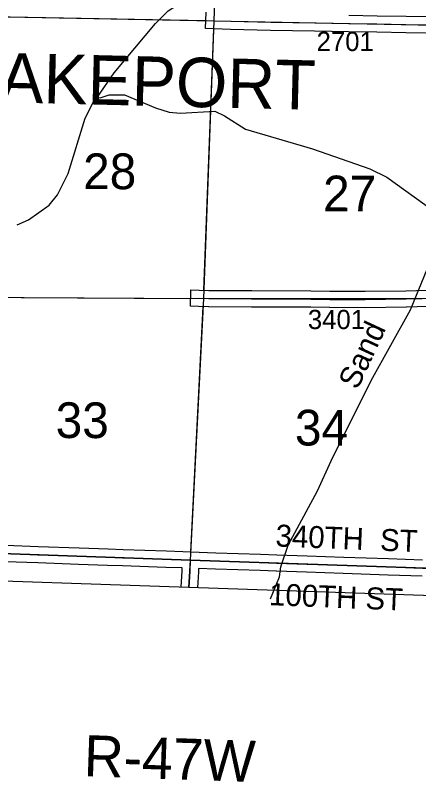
# Model space of a CAD drawing. Extents: x -157.2 to -99.3, y 12.2 to 46.2.
# Drawn here: x -144.708 to -143.24, y 16.379 to 19.169 of the extents above; entities that cross this region are included whole.
import ezdxf

# ---------------------------------------------------------------- set-up
doc = ezdxf.new("R2010")
doc.units = 0
for name, color, linetype in [('tdCoClipBndry', 7, 'Continuous'), ('tdCoCoAdjSecRdTxt', 7, 'Continuous'), ('tdCoCoBndry', 7, 'Continuous'), ('tdCoHydroRiver', 7, 'Continuous'), ('tdCoHydroTxtLg', 7, 'Continuous'), ('tdCoSecRdNmbr', 7, 'Continuous'), ('tdCoSecRdTxt', 7, 'Continuous'), ('tdCoSecRteBand', 7, 'Continuous'), ('tdCoSecRteCL', 7, 'Continuous'), ('tdCoSectLine', 7, 'Continuous'), ('tdCoSectLinePart', 7, 'Continuous'), ('tdCoSectNmbr', 7, 'Continuous'), ('tdCoSurfConc', 7, 'Continuous'), ('tdCoSurfEarth', 7, 'Continuous'), ('tdCoSurfGravel', 7, 'Continuous'), ('tdCoTwpBndryShd', 7, 'Continuous'), ('tdCoTwpNameTxt', 7, 'Continuous'), ('tdCoTwpRngTxt', 7, 'Continuous')]:
    doc.layers.add(name, color=color, linetype=linetype)

msp = doc.modelspace()

# ---------------------------------------------------------------- linework, layer by layer
at = {"layer": 'tdCoClipBndry'}
msp.add_lwpolyline([(-136.1344, 16.7663), (-142.0845, 17.0183), (-145.0729, 17.1202)], dxfattribs=at)
at = {"layer": 'tdCoCoBndry'}
msp.add_lwpolyline([(-146.5016, 17.2735), (-146.0768, 17.2556), (-146.0694, 17.2557), (-145.0695, 17.2201), (-144.0702, 17.1857), (-143.0731, 17.1519), (-142.0807, 17.1182), (-141.0904, 17.0763), (-140.1006, 17.0343), (-139.109, 16.9941), (-138.1248, 16.9495), (-137.1248, 16.9061), (-136.1296, 16.8661), (-135.1553, 16.8138), (-134.1666, 16.7512)], dxfattribs=at)
at = {"layer": 'tdCoHydroRiver'}
for points in [[(-144.4096, 18.8702), (-144.3483, 18.9598), (-144.1971, 19.1395), (-144.1514, 19.1854), (-144.1176, 19.2064), (-144.0962, 19.2309), (-144.0908, 19.2529), (-144.0964, 19.2752), (-144.1172, 19.3138), (-144.1521, 19.356), (-144.221, 19.4688), (-144.2911, 19.5438), (-144.3641, 19.6106)], [(-144.7011, 18.4061), (-144.6595, 18.4237), (-144.5851, 18.4781), (-144.5539, 18.5149), (-144.5151, 18.5926), (-144.4532, 18.7943), (-144.4177, 18.8658), (-144.4096, 18.8702)], [(-144.4096, 18.8702), (-144.3986, 18.8683), (-144.3667, 18.8799), (-144.3099, 18.8795), (-144.1978, 18.8316), (-144.1478, 18.8157), (-144.1069, 18.8128), (-143.9819, 18.8197), (-143.9462, 18.8027), (-143.8704, 18.7544), (-143.6265, 18.6831), (-143.4174, 18.6098), (-143.3553, 18.5793), (-143.1872, 18.4584), (-143.1614, 18.4291), (-143.1331, 18.3776)], [(-143.7788, 17.0444), (-143.7458, 17.125), (-143.7414, 17.1612), (-143.7152, 17.2393), (-143.6076, 17.4379), (-143.5582, 17.5468), (-143.4128, 17.8389), (-143.2702, 18.0963), (-143.1792, 18.3191), (-143.1493, 18.3639), (-143.1331, 18.3776)]]:
    msp.add_lwpolyline(points, dxfattribs=at)
at = {"layer": 'tdCoSecRteBand'}
for points in [[(-143.4944, 19.1691), (-143.3914, 19.1672), (-143.2857, 19.1654), (-143.2857, 19.1654), (-143.2856, 19.1654), (-143.1409, 19.163), (-143.1408, 19.163), (-143.1407, 19.163), (-143.0232, 19.1604), (-143.0212, 19.215)], [(-143.142, 19.103), (-143.2867, 19.1054), (-143.3924, 19.1072), (-143.3925, 19.1072), (-143.3925, 19.1072), (-143.4956, 19.1091), (-143.4956, 19.1091), (-143.4956, 19.1091), (-143.6188, 19.1116), (-143.7788, 19.1138), (-143.7789, 19.1138), (-143.779, 19.1138), (-143.9245, 19.117), (-143.9248, 19.117), (-143.925, 19.117), (-143.9852, 19.1193), (-144.0151, 19.1204), (-144.0129, 19.1803)], [(-143.1675, 18.1095), (-143.2846, 18.1063), (-143.2848, 18.1063), (-143.285, 18.1063), (-143.4347, 18.1043), (-143.435, 18.1043), (-143.4352, 18.1043), (-143.5635, 18.1048), (-143.5636, 18.1048), (-143.5638, 18.1048), (-143.6327, 18.1058), (-143.8478, 18.1068), (-144.0041, 18.1073), (-144.0046, 18.1073), (-144.0051, 18.1073), (-144.0408, 18.1085), (-144.0708, 18.1096), (-144.0687, 18.1695), (-144.0388, 18.1685), (-144.0035, 18.1673), (-143.8476, 18.1668), (-143.8476, 18.1668), (-143.8475, 18.1668), (-143.6323, 18.1658), (-143.6321, 18.1658), (-143.632, 18.1658), (-143.5631, 18.1648), (-143.4352, 18.1643), (-143.286, 18.1663), (-143.1688, 18.1695)], [(-144.7429, 17.2394), (-144.6243, 17.2353), (-144.4753, 17.2301), (-144.4753, 17.2301), (-144.4753, 17.2301), (-144.3702, 17.2264), (-144.3702, 17.2264), (-144.3701, 17.2264), (-144.3157, 17.2242), (-144.158, 17.219), (-144.1579, 17.219), (-144.1579, 17.219), (-144.0987, 17.2168), (-144.0689, 17.2157), (-144.039, 17.2148), (-144.039, 17.2146), (-144.0388, 17.2146), (-143.9777, 17.2123), (-143.8152, 17.2071), (-143.8151, 17.2071), (-143.8151, 17.2071), (-143.7557, 17.2049), (-143.646, 17.2012), (-143.646, 17.2012), (-143.646, 17.2012), (-143.5128, 17.1965), (-143.3493, 17.1909), (-143.2255, 17.1867)], [(-144.1045, 17.0872), (-144.101, 17.1459), (-144.1007, 17.1568), (-144.16, 17.159), (-144.3178, 17.1642), (-144.3179, 17.1642), (-144.318, 17.1642), (-144.3724, 17.1664), (-144.4774, 17.1701), (-144.6263, 17.1753), (-144.6264, 17.1753), (-144.6264, 17.1753), (-144.7448, 17.1795), (-144.8628, 17.1824), (-144.863, 17.1824), (-144.8632, 17.1824), (-144.9731, 17.1866), (-145.0409, 17.189), (-145.0451, 17.1192)], [(-143.2276, 17.1267), (-143.3514, 17.1309), (-143.3514, 17.1309), (-143.3514, 17.1309), (-143.5149, 17.1366), (-143.5149, 17.1366), (-143.5149, 17.1366), (-143.648, 17.1413), (-143.7578, 17.145), (-143.7578, 17.145), (-143.7579, 17.145), (-143.8172, 17.1472), (-143.9797, 17.1524), (-143.9797, 17.1524), (-143.9798, 17.1524), (-144.0408, 17.1546), (-144.0411, 17.1437), (-144.0411, 17.1433), (-144.0411, 17.1428), (-144.0446, 17.0851)]]:
    msp.add_lwpolyline(points, dxfattribs=at)
at = {"layer": 'tdCoSecRteCL'}
for points in [[(-143.9841, 19.1492), (-143.9239, 19.147), (-143.7784, 19.1438), (-143.6183, 19.1416), (-143.495, 19.1391), (-143.3919, 19.1372), (-143.2862, 19.1354), (-143.1414, 19.133), (-142.9942, 19.1297)], [(-144.0398, 18.1385), (-144.004, 18.1373), (-143.8477, 18.1368), (-143.6324, 18.1358), (-143.5633, 18.1348), (-143.4351, 18.1343), (-143.2854, 18.1363), (-143.168, 18.1395), (-143.0519, 18.1403), (-143.0306, 18.1392)], [(-145.0691, 17.2201), (-144.972, 17.2166), (-144.862, 17.2124), (-144.7439, 17.2095), (-144.6253, 17.2053), (-144.4764, 17.2001), (-144.3713, 17.1964), (-144.3168, 17.1942), (-144.159, 17.189), (-144.0699, 17.1857)], [(-144.0746, 17.0861), (-144.0711, 17.1446), (-144.0699, 17.1857)], [(-144.0699, 17.1857), (-143.9787, 17.1823), (-143.8162, 17.1772), (-143.7568, 17.1749), (-143.647, 17.1712), (-143.5138, 17.1666), (-143.3503, 17.1609), (-143.2265, 17.1567), (-143.1222, 17.1532), (-143.0727, 17.1519)]]:
    msp.add_lwpolyline(points, dxfattribs=at)
at = {"layer": 'tdCoSectLine'}
for points in [[(-143.9844, 19.1492), (-143.9501, 20.1393)], [(-144.9877, 19.1678), (-143.9844, 19.1492)], [(-144.0223, 18.1379), (-143.9844, 19.1492)], [(-143.9844, 19.1492), (-142.9946, 19.1297)], [(-144.894, 18.1425), (-144.0223, 18.1379)], [(-144.0702, 17.1857), (-144.0223, 18.1379)], [(-144.0223, 18.1379), (-143.031, 18.1392)], [(-145.0695, 17.2201), (-144.0702, 17.1857)], [(-144.0759, 17.0862), (-144.0702, 17.1857)], [(-144.0702, 17.1857), (-143.0731, 17.1519)]]:
    msp.add_lwpolyline(points, dxfattribs=at)
at = {"layer": 'tdCoSectLinePart'}
for points in [[(-144.9877, 19.1678), (-144.0144, 19.1498)], [(-144.0212, 18.1679), (-143.9856, 19.1193)], [(-144.894, 18.1425), (-144.0702, 18.1382)], [(-144.0687, 17.2161), (-144.0238, 18.108)]]:
    msp.add_lwpolyline(points, dxfattribs=at)
at = {"layer": 'tdCoSurfConc'}
msp.add_lwpolyline([(-144.0398, 18.1385), (-144.004, 18.1373), (-143.8477, 18.1368), (-143.6324, 18.1358), (-143.5633, 18.1348), (-143.4351, 18.1343), (-143.2854, 18.1363), (-143.168, 18.1395), (-143.0519, 18.1403), (-143.0306, 18.1392)], dxfattribs=at)
at = {"layer": 'tdCoSurfEarth'}
msp.add_lwpolyline([(-144.0746, 17.0861), (-144.0711, 17.1446), (-144.0699, 17.1857)], dxfattribs=at)
at = {"layer": 'tdCoSurfGravel'}
for points in [[(-143.9841, 19.1492), (-143.9239, 19.147), (-143.7784, 19.1438), (-143.6183, 19.1416), (-143.495, 19.1391), (-143.3919, 19.1372), (-143.2862, 19.1354), (-143.1414, 19.133), (-142.9942, 19.1297), (-142.9345, 19.1288), (-142.8092, 19.1243), (-142.6879, 19.1209), (-142.5974, 19.1164), (-142.4701, 19.1125), (-142.3853, 19.1093), (-142.2825, 19.1058), (-142.1604, 19.1019), (-142.0383, 19.0984), (-142.0151, 19.0978)], [(-145.0691, 17.2201), (-144.972, 17.2166), (-144.862, 17.2124), (-144.7439, 17.2095), (-144.6253, 17.2053), (-144.4764, 17.2001), (-144.3713, 17.1964), (-144.3168, 17.1942), (-144.159, 17.189), (-144.0699, 17.1857), (-143.9787, 17.1823), (-143.8162, 17.1772), (-143.7568, 17.1749), (-143.647, 17.1712), (-143.5138, 17.1666), (-143.3503, 17.1609), (-143.2265, 17.1567), (-143.1222, 17.1532), (-143.0727, 17.1519)]]:
    msp.add_lwpolyline(points, dxfattribs=at)
at = {"layer": 'tdCoTwpBndryShd'}
msp.add_lwpolyline([(-140.1006, 17.0343), (-141.0904, 17.0763), (-142.0807, 17.1182), (-143.0731, 17.1519), (-144.0702, 17.1857), (-145.0695, 17.2201)], dxfattribs=at)

# ---------------------------------------------------------------- texts
at = {"layer": 'tdCoCoAdjSecRdTxt'}
msp.add_text('100TH ST', height=0.08, rotation=357.6693, dxfattribs=at).set_placement((-143.7854, 17.0217))
at = {"layer": 'tdCoHydroTxtLg'}
msp.add_text('Sand', height=0.08, rotation=65.1149, dxfattribs=at).set_placement((-143.4625, 17.8028))
at = {"layer": 'tdCoSecRdNmbr'}
for s, rotation, p in [('2701', 359.8904, (-143.6114, 19.039)), ('3401', 359.8903, (-143.6432, 18.0267))]:
    msp.add_text(s, height=0.07, rotation=rotation, dxfattribs=at).set_placement(p)
at = {"layer": 'tdCoSecRdTxt'}
msp.add_text('340TH  ST', height=0.08, rotation=357.6693, dxfattribs=at).set_placement((-143.7619, 17.2354))
at = {"layer": 'tdCoSectNmbr'}
for s, rotation, p in [('28', 359.8897, (-144.4611, 18.5361)), ('27', 359.8904, (-143.5879, 18.4552)), ('33', 359.8896, (-144.561, 17.63)), ('34', 359.8903, (-143.6904, 17.6028))]:
    msp.add_text(s, height=0.13, rotation=rotation, dxfattribs=at).set_placement(p)
at = {"layer": 'tdCoTwpNameTxt'}
msp.add_text('LAKEPORT', height=0.18, rotation=358.5901, dxfattribs=at).set_placement((-144.9012, 18.8559))
at = {"layer": 'tdCoTwpRngTxt'}
msp.add_text('R-47W', height=0.15, rotation=358.0306, dxfattribs=at).set_placement((-144.4603, 16.3989))

doc.saveas('drawing.dxf')
